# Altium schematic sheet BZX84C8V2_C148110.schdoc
size 127 x 101 mm
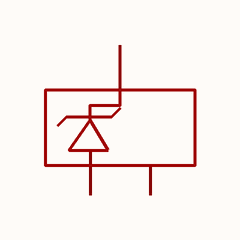
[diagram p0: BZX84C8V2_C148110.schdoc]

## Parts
D?  bzx84c8v2_c148110  [SOT-23-3_L3.0-W1.7-P0.95-LS2.9-BR]  (value not drawn)

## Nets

Not connected (* = marked no-connect by the designer): D? 1(A) 2 3(K)

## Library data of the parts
D? = bzx84c8v2_c148110: 二极管配置:1个独立式;稳压值(标称值):8.2V;稳压值(范围):7.7V~8.7V;耗散功率(Pd):300mW;; Manufacturer: CJ(江苏长电/长晶); AddInBom: yes; ModelId: 89cb27a44ab2466697082bb9fd73a7d0; ModelName: SOT-23-3L_L2.9-W1.6-H1.1-LS2.8-P0.95; ModelTransform: 114.173,110.236,0,90,0,0,0,0,0; Diode Configuration: 1个独立式; Zener Voltage(Nom): 8.2V; Reverse Leakage Current (Ir): 700nA; Pd - Power Dissipation: 300mW; Impedance(Zzt): 15Ω; Impedance(Zzk): 80Ω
